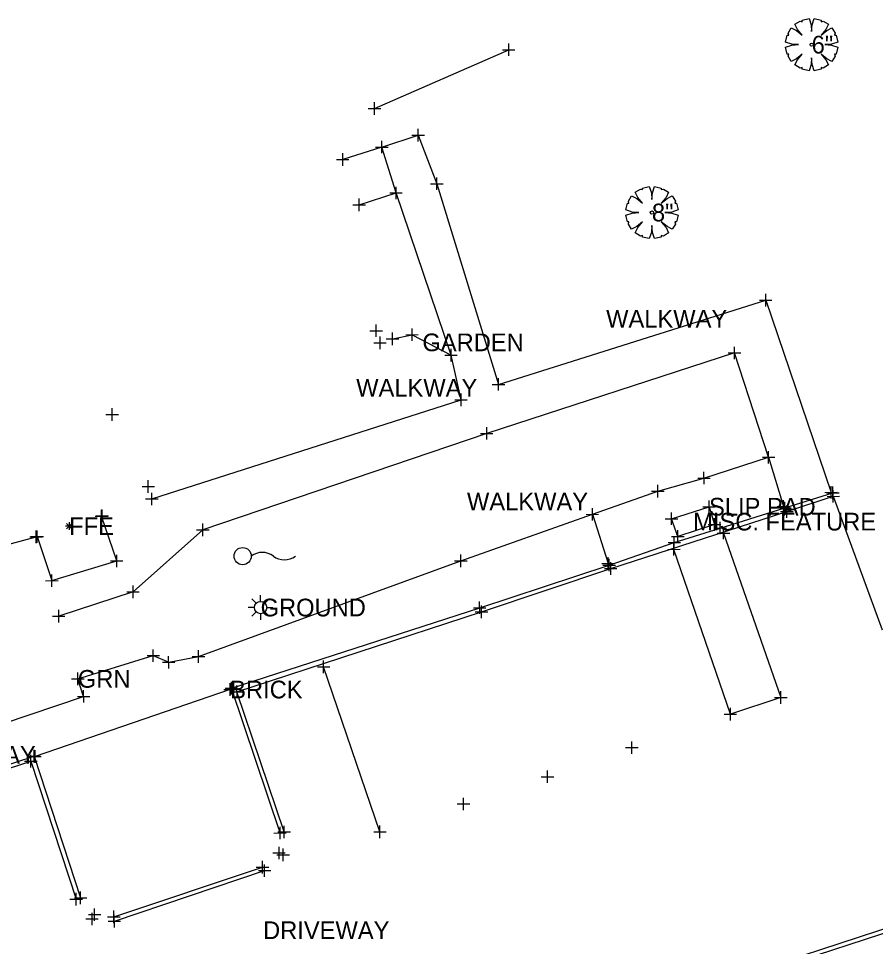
# Model space of a CAD drawing. Extents: x 1729655 to 1739338, y 463812 to 469501.
# Drawn here: x 1734985 to 1735072.1, y 466921 to 467015.3 of the extents above; entities that cross this region are included whole.
import ezdxf

# ---------------------------------------------------------------- set-up
doc = ezdxf.new("R2010")
doc.units = 0
for name, color, linetype in [('S_Bridge_Column_Round', 7, 'Continuous'), ('S_Bridge_Deck', 7, 'Continuous'), ('S_Buildings_Steps', 7, 'Continuous'), ('S_Curb_Type_2', 7, 'Continuous'), ('S_Curb_Type_5', 7, 'Continuous'), ('S_Drainage_Invert_Culvert', 7, 'Continuous'), ('S_Ground_SpotElevation', 7, 'Continuous'), ('S_Property_Garden', 7, 'Continuous'), ('S_Roadway_Drive_Gravel', 7, 'Continuous'), ('S_Roadway_Edge_TW', 7, 'Continuous'), ('S_Roadway_Sidewalks', 7, 'Continuous'), ('S_Terrain_High_Points', 7, 'Continuous'), ('S_Trees_Decid_NonPay', 7, 'Continuous'), ('S_Trees_TreeLine', 7, 'Continuous'), ('S_Utilities_UG_Sanitary_MH', 7, 'Continuous')]:
    doc.layers.add(name, color=color, linetype=linetype)

msp = doc.modelspace()

# ---------------------------------------------------------------- linework, layer by layer
at = {"layer": 'S_Bridge_Column_Round'}
for p, q in [((1735034.805, 467011.529), (1735034.803, 467012.801)), ((1735034.168, 467012.164), (1735035.44, 467012.166)), ((1735034.804, 467012.165), (1735034.804, 467012.165)), ((1735020.534, 467006.184), (1735021.806, 467006.186)), ((1735021.171, 467005.549), (1735021.169, 467006.821)), ((1735021.17, 467006.185), (1735021.17, 467006.185)), ((1735025.604, 467002.846), (1735025.602, 467004.118)), ((1735024.967, 467003.481), (1735026.239, 467003.483)), ((1735025.603, 467003.482), (1735025.603, 467003.482)), ((1735021.283, 467002.269), (1735022.555, 467002.271)), ((1735021.283, 467002.269), (1735022.555, 467002.271)), ((1735021.92, 467001.634), (1735021.918, 467002.906)), ((1735021.92, 467001.634), (1735021.918, 467002.906)), ((1735021.919, 467002.27), (1735021.919, 467002.27)), ((1735021.919, 467002.27), (1735021.919, 467002.27)), ((1735017.934, 467000.375), (1735017.932, 467001.647)), ((1735017.297, 467001.01), (1735018.569, 467001.012)), ((1735017.933, 467001.011), (1735017.933, 467001.011)), ((1735026.855, 466998.541), (1735028.127, 466998.543)), ((1735027.492, 466997.906), (1735027.49, 466999.178)), ((1735027.491, 466998.542), (1735027.491, 466998.542)), ((1735022.717, 466997.605), (1735023.989, 466997.607)), ((1735022.717, 466997.605), (1735023.989, 466997.607)), ((1735023.354, 466996.97), (1735023.352, 466998.242)), ((1735023.354, 466996.97), (1735023.352, 466998.242)), ((1735023.353, 466997.606), (1735023.353, 466997.606)), ((1735023.353, 466997.606), (1735023.353, 466997.606)), ((1735019.613, 466995.766), (1735019.611, 466997.038)), ((1735018.976, 466996.401), (1735020.248, 466996.403)), ((1735019.612, 466996.402), (1735019.612, 466996.402)), ((1735060.922, 466986.063), (1735060.92, 466987.335)), ((1735060.285, 466986.698), (1735061.557, 466986.7)), ((1735060.921, 466986.699), (1735060.921, 466986.699)), ((1735020.7, 466983.598), (1735021.972, 466983.6)), ((1735021.337, 466982.963), (1735021.335, 466984.235)), ((1735021.336, 466983.599), (1735021.336, 466983.599)), ((1735022.986, 466982.13), (1735022.984, 466983.402)), ((1735022.986, 466982.13), (1735022.984, 466983.402)), ((1735024.979, 466982.56), (1735024.977, 466983.832)), ((1735021.093, 466982.369), (1735022.365, 466982.371)), ((1735021.73, 466981.734), (1735021.728, 466983.006)), ((1735021.729, 466982.37), (1735021.729, 466982.37)), ((1735022.349, 466982.765), (1735023.621, 466982.767)), ((1735022.349, 466982.765), (1735023.621, 466982.767)), ((1735022.985, 466982.766), (1735022.985, 466982.766)), ((1735022.985, 466982.766), (1735022.985, 466982.766)), ((1735024.342, 466983.195), (1735025.614, 466983.197)), ((1735024.978, 466983.196), (1735024.978, 466983.196)), ((1735028.946, 466980.48), (1735028.944, 466981.752)), ((1735028.946, 466980.48), (1735028.944, 466981.752)), ((1735057.745, 466980.703), (1735057.743, 466981.975)), ((1735028.309, 466981.115), (1735029.581, 466981.117)), ((1735028.309, 466981.115), (1735029.581, 466981.117)), ((1735028.945, 466981.116), (1735028.945, 466981.116)), ((1735028.945, 466981.116), (1735028.945, 466981.116)), ((1735057.108, 466981.338), (1735058.38, 466981.34)), ((1735057.744, 466981.339), (1735057.744, 466981.339)), ((1735033.759, 466977.505), (1735033.757, 466978.777)), ((1735033.122, 466978.14), (1735034.394, 466978.142)), ((1735033.758, 466978.141), (1735033.758, 466978.141)), ((1735029.959, 466975.944), (1735029.957, 466977.216)), ((1735029.322, 466976.579), (1735030.594, 466976.581)), ((1735029.958, 466976.58), (1735029.958, 466976.58)), ((1734993.876, 466975.072), (1734995.148, 466975.074)), ((1734994.513, 466974.437), (1734994.511, 466975.709)), ((1734994.512, 466975.073), (1734994.512, 466975.073)), ((1735031.928, 466973.163), (1735033.2, 466973.165)), ((1735032.565, 466972.528), (1735032.563, 466973.8)), ((1735032.564, 466973.164), (1735032.564, 466973.164)), ((1735061.214, 466970.095), (1735061.212, 466971.367)), ((1735061.214, 466970.095), (1735061.212, 466971.367)), ((1735060.577, 466970.73), (1735061.849, 466970.732)), ((1735060.577, 466970.73), (1735061.849, 466970.732)), ((1735061.213, 466970.731), (1735061.213, 466970.731)), ((1735061.213, 466970.731), (1735061.213, 466970.731)), ((1735054.648, 466967.985), (1735054.646, 466969.257)), ((1734998.177, 466967.128), (1734998.175, 466968.4)), ((1735054.011, 466968.62), (1735055.283, 466968.622)), ((1735054.647, 466968.621), (1735054.647, 466968.621)), ((1734997.54, 466967.763), (1734998.812, 466967.765)), ((1734998.176, 466967.764), (1734998.176, 466967.764)), ((1735049.322, 466967.286), (1735050.594, 466967.288)), ((1735049.959, 466966.651), (1735049.957, 466967.923)), ((1735049.958, 466967.287), (1735049.958, 466967.287)), ((1735067.559, 466966.531), (1735067.557, 466967.803)), ((1735067.732, 466966.488), (1735067.73, 466967.76)), ((1735067.784, 466966.125), (1735067.782, 466967.397)), ((1734997.91, 466966.492), (1734999.182, 466966.494)), ((1734997.91, 466966.492), (1734999.182, 466966.494)), ((1734998.547, 466965.857), (1734998.545, 466967.129)), ((1734998.547, 466965.857), (1734998.545, 466967.129)), ((1734998.546, 466966.493), (1734998.546, 466966.493)), ((1734998.546, 466966.493), (1734998.546, 466966.493)), ((1735055.161, 466965.065), (1735055.159, 466966.337)), ((1735062.715, 466965.088), (1735062.713, 466966.36)), ((1735066.922, 466967.166), (1735068.194, 466967.168)), ((1735067.095, 466967.123), (1735068.367, 466967.125)), ((1735067.147, 466966.76), (1735068.419, 466966.762)), ((1735067.558, 466967.167), (1735067.558, 466967.167)), ((1735067.731, 466967.124), (1735067.731, 466967.124)), ((1735067.783, 466966.761), (1735067.783, 466966.761)), ((1734993.427, 466964.111), (1734993.425, 466965.383)), ((1734993.508, 466964.156), (1734993.506, 466965.428)), ((1735043.306, 466964.295), (1735043.304, 466965.567)), ((1735043.306, 466964.295), (1735043.304, 466965.567)), ((1735054.524, 466965.7), (1735055.796, 466965.702)), ((1735055.16, 466965.701), (1735055.16, 466965.701)), ((1735062.078, 466965.723), (1735063.35, 466965.725)), ((1735062.229, 466965.581), (1735063.501, 466965.583)), ((1735062.714, 466965.724), (1735062.714, 466965.724)), ((1735062.866, 466964.946), (1735062.864, 466966.218)), ((1735062.865, 466965.582), (1735062.865, 466965.582)), ((1735063.06, 466964.57), (1735063.058, 466965.842)), ((1734992.79, 466964.746), (1734994.062, 466964.748)), ((1734992.871, 466964.791), (1734994.143, 466964.793)), ((1734993.426, 466964.747), (1734993.426, 466964.747)), ((1734993.507, 466964.792), (1734993.507, 466964.792)), ((1735042.669, 466964.93), (1735043.941, 466964.932)), ((1735042.669, 466964.93), (1735043.941, 466964.932)), ((1735043.305, 466964.931), (1735043.305, 466964.931)), ((1735043.305, 466964.931), (1735043.305, 466964.931)), ((1735050.714, 466964.483), (1735051.986, 466964.485)), ((1735051.351, 466963.848), (1735051.349, 466965.12)), ((1735051.35, 466964.484), (1735051.35, 466964.484)), ((1735055.715, 466963.254), (1735055.713, 466964.526)), ((1735062.423, 466965.205), (1735063.695, 466965.207)), ((1735063.059, 466965.206), (1735063.059, 466965.206)), ((1735003.721, 466962.716), (1735003.719, 466963.988)), ((1735055.078, 466963.889), (1735056.35, 466963.891)), ((1735055.652, 466963.54), (1735056.924, 466963.542)), ((1735055.714, 466963.89), (1735055.714, 466963.89)), ((1735056.289, 466962.905), (1735056.287, 466964.177)), ((1735056.288, 466963.541), (1735056.288, 466963.541)), ((1735056.624, 466962.395), (1735056.622, 466963.667)), ((1734986.134, 466962.645), (1734987.406, 466962.647)), ((1734986.247, 466962.666), (1734987.519, 466962.668)), ((1734986.771, 466962.01), (1734986.769, 466963.282)), ((1734986.77, 466962.646), (1734986.77, 466962.646)), ((1734986.884, 466962.031), (1734986.882, 466963.303)), ((1734986.883, 466962.667), (1734986.883, 466962.667)), ((1735003.084, 466963.351), (1735004.356, 466963.353)), ((1735003.72, 466963.352), (1735003.72, 466963.352)), ((1735051.358, 466962.667), (1735052.63, 466962.669)), ((1735051.629, 466961.417), (1735051.627, 466962.689)), ((1735051.995, 466962.032), (1735051.993, 466963.304)), ((1735051.994, 466962.668), (1735051.994, 466962.668)), ((1735055.987, 466963.03), (1735057.259, 466963.032)), ((1735056.623, 466963.031), (1735056.623, 466963.031)), ((1735050.992, 466962.052), (1735052.264, 466962.054)), ((1735051.598, 466960.736), (1735051.596, 466962.008)), ((1735051.628, 466962.053), (1735051.628, 466962.053)), ((1734994.971, 466959.557), (1734994.969, 466960.829)), ((1735029.941, 466959.563), (1735029.939, 466960.835)), ((1735050.961, 466961.371), (1735052.233, 466961.373)), ((1735051.597, 466961.372), (1735051.597, 466961.372)), ((1734994.334, 466960.192), (1734995.606, 466960.194)), ((1734994.97, 466960.193), (1734994.97, 466960.193)), ((1735029.304, 466960.198), (1735030.576, 466960.2)), ((1735029.94, 466960.199), (1735029.94, 466960.199)), ((1735044.258, 466959.929), (1735045.53, 466959.931)), ((1735044.376, 466959.775), (1735045.648, 466959.777)), ((1735044.895, 466959.294), (1735044.893, 466960.566)), ((1735044.894, 466959.93), (1735044.894, 466959.93)), ((1735045.013, 466959.14), (1735045.011, 466960.412)), ((1735045.012, 466959.776), (1735045.012, 466959.776)), ((1735045.17, 466958.784), (1735045.168, 466960.056)), ((1734988.386, 466957.551), (1734988.384, 466958.823)), ((1735044.533, 466959.419), (1735045.805, 466959.421)), ((1735045.169, 466959.42), (1735045.169, 466959.42)), ((1734987.749, 466958.186), (1734989.021, 466958.188)), ((1734988.385, 466958.187), (1734988.385, 466958.187)), ((1734995.994, 466957.057), (1734997.266, 466957.059)), ((1734995.994, 466957.057), (1734997.266, 466957.059)), ((1734996.631, 466956.422), (1734996.629, 466957.694)), ((1734996.631, 466956.422), (1734996.629, 466957.694)), ((1734996.63, 466957.058), (1734996.63, 466957.058)), ((1734996.63, 466957.058), (1734996.63, 466957.058)), ((1735031.853, 466954.803), (1735031.851, 466956.075)), ((1734989.076, 466953.949), (1734989.074, 466955.221)), ((1734989.076, 466953.949), (1734989.074, 466955.221)), ((1734989.076, 466953.949), (1734989.074, 466955.221)), ((1735031.216, 466955.438), (1735032.488, 466955.44)), ((1735031.407, 466955.016), (1735032.679, 466955.018)), ((1735031.852, 466955.439), (1735031.852, 466955.439)), ((1735032.044, 466954.381), (1735032.042, 466955.653)), ((1735032.043, 466955.017), (1735032.043, 466955.017)), ((1734988.439, 466954.584), (1734989.711, 466954.586)), ((1734988.439, 466954.584), (1734989.711, 466954.586)), ((1734988.439, 466954.584), (1734989.711, 466954.586)), ((1734989.075, 466954.585), (1734989.075, 466954.585)), ((1734989.075, 466954.585), (1734989.075, 466954.585)), ((1734989.075, 466954.585), (1734989.075, 466954.585)), ((1734998.05, 466950.567), (1734999.322, 466950.569)), ((1734998.05, 466950.567), (1734999.322, 466950.569)), ((1734998.687, 466949.932), (1734998.685, 466951.204)), ((1734998.687, 466949.932), (1734998.685, 466951.204)), ((1734998.686, 466950.568), (1734998.686, 466950.568)), ((1734998.686, 466950.568), (1734998.686, 466950.568)), ((1735000.25, 466949.252), (1735000.248, 466950.524)), ((1735002.639, 466950.47), (1735003.911, 466950.472)), ((1735003.276, 466949.835), (1735003.274, 466951.107)), ((1735003.275, 466950.471), (1735003.275, 466950.471)), ((1734999.613, 466949.887), (1735000.885, 466949.889)), ((1735000.249, 466949.888), (1735000.249, 466949.888)), ((1735015.357, 466949.433), (1735016.629, 466949.435)), ((1735015.994, 466948.798), (1735015.992, 466950.07)), ((1735015.993, 466949.434), (1735015.993, 466949.434)), ((1734991.019, 466947.568), (1734991.017, 466948.84)), ((1734991.019, 466947.568), (1734991.017, 466948.84)), ((1734990.382, 466948.203), (1734991.654, 466948.205)), ((1734990.382, 466948.203), (1734991.654, 466948.205)), ((1734991.018, 466948.204), (1734991.018, 466948.204)), ((1734991.018, 466948.204), (1734991.018, 466948.204)), ((1735006.502, 466946.484), (1735006.5, 466947.756)), ((1735006.623, 466946.619), (1735006.621, 466947.891)), ((1735007.193, 466946.246), (1735007.191, 466947.518)), ((1734991.611, 466945.789), (1734991.609, 466947.061)), ((1735005.865, 466947.119), (1735007.137, 466947.121)), ((1735005.986, 466947.254), (1735007.258, 466947.256)), ((1735006.501, 466947.12), (1735006.501, 466947.12)), ((1735006.556, 466946.881), (1735007.828, 466946.883)), ((1735006.622, 466947.255), (1735006.622, 466947.255)), ((1735007.192, 466946.882), (1735007.192, 466946.882)), ((1735062.461, 466945.68), (1735062.459, 466946.952)), ((1734990.974, 466946.424), (1734992.246, 466946.426)), ((1734991.61, 466946.425), (1734991.61, 466946.425)), ((1735061.824, 466946.315), (1735063.096, 466946.317)), ((1735062.46, 466946.316), (1735062.46, 466946.316)), ((1735057.33, 466943.972), (1735057.328, 466945.244)), ((1735056.693, 466944.607), (1735057.965, 466944.609)), ((1735057.329, 466944.608), (1735057.329, 466944.608)), ((1735047.307, 466940.58), (1735047.305, 466941.852)), ((1734986.567, 466939.704), (1734986.565, 466940.976)), ((1734986.668, 466939.676), (1734986.666, 466940.948)), ((1735046.67, 466941.215), (1735047.942, 466941.217)), ((1735047.306, 466941.216), (1735047.306, 466941.216)), ((1734985.93, 466940.339), (1734987.202, 466940.341)), ((1734986.031, 466940.311), (1734987.303, 466940.313)), ((1734986.248, 466939.199), (1734986.246, 466940.471)), ((1734986.566, 466940.34), (1734986.566, 466940.34)), ((1734986.667, 466940.312), (1734986.667, 466940.312)), ((1734985.611, 466939.834), (1734986.883, 466939.836)), ((1734986.247, 466939.835), (1734986.247, 466939.835)), ((1735038.113, 466938.257), (1735039.385, 466938.259)), ((1735038.75, 466937.622), (1735038.748, 466938.894)), ((1735038.749, 466938.258), (1735038.749, 466938.258)), ((1735029.568, 466935.487), (1735030.84, 466935.489)), ((1735030.205, 466934.852), (1735030.203, 466936.124)), ((1735030.204, 466935.488), (1735030.204, 466935.488)), ((1735010.931, 466932.532), (1735012.203, 466932.534)), ((1735011.34, 466932.636), (1735012.612, 466932.638)), ((1735011.568, 466931.897), (1735011.566, 466933.169)), ((1735011.567, 466932.533), (1735011.567, 466932.533)), ((1735011.977, 466932.001), (1735011.975, 466933.273)), ((1735011.976, 466932.637), (1735011.976, 466932.637)), ((1735021.083, 466932.651), (1735022.355, 466932.653)), ((1735021.72, 466932.016), (1735021.718, 466933.288)), ((1735021.719, 466932.652), (1735021.719, 466932.652)), ((1735010.828, 466930.505), (1735012.1, 466930.507)), ((1735011.465, 466929.87), (1735011.463, 466931.142)), ((1735011.464, 466930.506), (1735011.464, 466930.506)), ((1735011.878, 466929.684), (1735011.876, 466930.956)), ((1735009.792, 466928.43), (1735009.79, 466929.702)), ((1735011.241, 466930.319), (1735012.513, 466930.321)), ((1735011.877, 466930.32), (1735011.877, 466930.32)), ((1735009.155, 466929.065), (1735010.427, 466929.067)), ((1735009.361, 466928.705), (1735010.633, 466928.707)), ((1735009.791, 466929.066), (1735009.791, 466929.066)), ((1735009.998, 466928.07), (1735009.996, 466929.342)), ((1735009.997, 466928.706), (1735009.997, 466928.706)), ((1734990.214, 466925.8), (1734991.486, 466925.802)), ((1734990.664, 466925.936), (1734991.936, 466925.938)), ((1734990.851, 466925.165), (1734990.849, 466926.437)), ((1734990.85, 466925.801), (1734990.85, 466925.801)), ((1734991.301, 466925.301), (1734991.299, 466926.573)), ((1734991.3, 466925.937), (1734991.3, 466925.937)), ((1734992.725, 466923.596), (1734992.723, 466924.868)), ((1734992.088, 466924.231), (1734993.36, 466924.233)), ((1734992.461, 466923.158), (1734992.459, 466924.43)), ((1734992.724, 466924.232), (1734992.724, 466924.232)), ((1734994.046, 466924.015), (1734995.318, 466924.017)), ((1734994.683, 466923.38), (1734994.681, 466924.652)), ((1734994.682, 466924.016), (1734994.682, 466924.016)), ((1734994.729, 466922.939), (1734994.727, 466924.211)), ((1734991.824, 466923.793), (1734993.096, 466923.795)), ((1734992.46, 466923.794), (1734992.46, 466923.794)), ((1734994.092, 466923.574), (1734995.364, 466923.576)), ((1734994.728, 466923.575), (1734994.728, 466923.575))]:
    msp.add_line(p, q, dxfattribs=at)
at = {"layer": 'S_Bridge_Deck'}
for p, q in [((1735009.149, 466955.896), (1735008.708, 466956.337)), ((1735009.59, 466956.079), (1735009.59, 466956.703)), ((1735010.031, 466955.896), (1735010.472, 466956.337)), ((1735008.966, 466955.455), (1735008.342, 466955.455)), ((1735009.149, 466955.014), (1735008.708, 466954.573)), ((1735010.031, 466955.014), (1735010.472, 466954.573)), ((1735010.214, 466955.455), (1735010.838, 466955.455)), ((1735009.59, 466954.831), (1735009.59, 466954.207))]:
    msp.add_line(p, q, dxfattribs=at)
msp.add_circle((1735009.59, 466955.455), 0.624, dxfattribs=at)
at = {"layer": 'S_Buildings_Steps'}
for p, q in [((1734990.534, 466963.731), (1734989.748, 466963.731)), ((1734990.403, 466963.469), (1734989.879, 466963.993)), ((1734990.403, 466963.993), (1734989.879, 466963.469)), ((1734990.141, 466964.124), (1734990.141, 466963.338))]:
    msp.add_line(p, q, dxfattribs=at)
at = {"layer": 'S_Curb_Type_2'}
msp.add_circle((1735007.767, 466960.685), 0.873, dxfattribs=at)
for centre, start, end in [((1735009.763, 466959.188), 53.1301, 126.8699), ((1735012.009, 466962.182), 233.1301, 306.8699)]:
    msp.add_arc(centre, 1.871, start, end, dxfattribs=at)
at = {"layer": 'S_Curb_Type_5'}
for points in [[(1735064.26, 467012.682), (1735063.571, 467012.735), (1735062.934, 467012.947), (1735063.093, 467013.637), (1735063.252, 467013.637), (1735063.199, 467013.849), (1735063.517, 467014.379), (1735064.047, 467014.114), (1735064.632, 467013.637), (1735064.154, 467014.22), (1735063.889, 467014.751), (1735064.419, 467015.069), (1735064.632, 467015.016), (1735064.632, 467015.175), (1735065.321, 467015.334), (1735065.533, 467014.698), (1735065.586, 467014.008), (1735065.639, 467014.698), (1735065.851, 467015.334), (1735066.541, 467015.175), (1735066.541, 467015.016), (1735066.753, 467015.069), (1735067.284, 467014.751), (1735067.018, 467014.22), (1735066.541, 467013.637), (1735067.124, 467014.114), (1735067.654, 467014.379), (1735067.973, 467013.849), (1735067.92, 467013.637), (1735068.079, 467013.637), (1735068.239, 467012.947), (1735067.602, 467012.735), (1735066.912, 467012.682), (1735067.602, 467012.629), (1735068.239, 467012.417), (1735068.079, 467011.727), (1735067.92, 467011.727), (1735067.973, 467011.515), (1735067.654, 467010.985), (1735067.124, 467011.25), (1735066.541, 467011.727), (1735067.018, 467011.144), (1735067.284, 467010.613), (1735066.753, 467010.295), (1735066.541, 467010.348), (1735066.541, 467010.189), (1735065.851, 467010.03), (1735065.639, 467010.666), (1735065.586, 467011.356), (1735065.533, 467010.666), (1735065.321, 467010.03), (1735064.632, 467010.189), (1735064.632, 467010.348), (1735064.419, 467010.295), (1735063.889, 467010.613), (1735064.154, 467011.144), (1735064.632, 467011.727), (1735064.047, 467011.25), (1735063.517, 467010.985), (1735063.199, 467011.515), (1735063.252, 467011.727), (1735063.093, 467011.727), (1735062.934, 467012.417), (1735063.571, 467012.629), (1735064.26, 467012.682)], [(1735048.031, 466995.614), (1735047.342, 466995.667), (1735046.705, 466995.879), (1735046.864, 466996.569), (1735047.023, 466996.569), (1735046.97, 466996.781), (1735047.288, 466997.311), (1735047.818, 466997.046), (1735048.403, 466996.569), (1735047.925, 466997.152), (1735047.66, 466997.683), (1735048.19, 466998.001), (1735048.403, 466997.948), (1735048.403, 466998.107), (1735049.092, 466998.266), (1735049.304, 466997.63), (1735049.357, 466996.94), (1735049.41, 466997.63), (1735049.622, 466998.266), (1735050.312, 466998.107), (1735050.312, 466997.948), (1735050.524, 466998.001), (1735051.055, 466997.683), (1735050.789, 466997.152), (1735050.312, 466996.569), (1735050.895, 466997.046), (1735051.425, 466997.311), (1735051.744, 466996.781), (1735051.691, 466996.569), (1735051.85, 466996.569), (1735052.01, 466995.879), (1735051.373, 466995.667), (1735050.683, 466995.614), (1735051.373, 466995.561), (1735052.01, 466995.349), (1735051.85, 466994.659), (1735051.691, 466994.659), (1735051.744, 466994.447), (1735051.425, 466993.917), (1735050.895, 466994.182), (1735050.312, 466994.659), (1735050.789, 466994.076), (1735051.055, 466993.545), (1735050.524, 466993.227), (1735050.312, 466993.28), (1735050.312, 466993.121), (1735049.622, 466992.962), (1735049.41, 466993.598), (1735049.357, 466994.288), (1735049.304, 466993.598), (1735049.092, 466992.962), (1735048.403, 466993.121), (1735048.403, 466993.28), (1735048.19, 466993.227), (1735047.66, 466993.545), (1735047.925, 466994.076), (1735048.403, 466994.659), (1735047.818, 466994.182), (1735047.288, 466993.917), (1735046.97, 466994.447), (1735047.023, 466994.659), (1735046.864, 466994.659), (1735046.705, 466995.349), (1735047.342, 466995.561), (1735048.031, 466995.614)]]:
    msp.add_lwpolyline(points, dxfattribs=at)
for centre in [(1735065.586, 467012.682), (1735049.357, 466995.614)]:
    msp.add_circle(centre, 0.166, dxfattribs=at)
at = {"layer": 'S_Drainage_Invert_Culvert'}
msp.add_lwpolyline([(1735022.985, 466982.766), (1735024.978, 466983.196), (1735028.945, 466981.116)], dxfattribs=at)
at = {"layer": 'S_Ground_SpotElevation'}
for p, q in [((1735063.059, 466965.206), (1735067.783, 466966.761)), ((1735067.783, 466966.761), (1735072.74, 466953.186)), ((1735045.169, 466959.42), (1735063.059, 466965.206)), ((1735032.043, 466955.017), (1735045.169, 466959.42)), ((1735007.192, 466946.882), (1735032.043, 466955.017)), ((1735011.976, 466932.637), (1735007.192, 466946.882)), ((1734959.798, 466931.066), (1734986.247, 466939.835)), ((1734986.247, 466939.835), (1734990.85, 466925.801)), ((1734994.728, 466923.575), (1735009.997, 466928.706)), ((1735092.82, 466929.33), (1735062.66, 466919.391))]:
    msp.add_line(p, q, dxfattribs=at)
at = {"layer": 'S_Property_Garden'}
for points in [[(1735021.919, 467002.27), (1735025.603, 467003.482), (1735027.491, 466998.542), (1735033.758, 466978.141), (1735060.921, 466986.699), (1735067.558, 466967.167)], [(1734998.546, 466966.493), (1735029.958, 466976.58), (1735028.945, 466981.116), (1735023.353, 466997.606)], [(1734998.686, 466950.568), (1735000.249, 466949.888), (1735003.275, 466950.471), (1735029.94, 466960.199), (1735043.305, 466964.931), (1735049.958, 466967.287), (1735054.647, 466968.621), (1735061.213, 466970.731), (1735057.744, 466981.339), (1735032.564, 466973.164), (1735003.72, 466963.352), (1734996.63, 466957.058)], [(1734950.694, 466952.682), (1734952.406, 466952.401), (1734980.826, 466960.286), (1734981.723, 466961.277), (1734986.77, 466962.646)], [(1734959.91, 466931.635), (1734958.83, 466935.374), (1734991.61, 466946.425), (1734991.018, 466948.204)]]:
    msp.add_lwpolyline(points, dxfattribs=at)
at = {"layer": 'S_Roadway_Drive_Gravel'}
for points in [[(1735056.623, 466963.031), (1735062.46, 466946.316), (1735057.329, 466944.608), (1735051.597, 466961.372)], [(1735021.719, 466932.652), (1735015.993, 466949.434)]]:
    msp.add_lwpolyline(points, dxfattribs=at)
at = {"layer": 'S_Roadway_Edge_TW'}
for points in [[(1734996.63, 466957.058), (1734989.075, 466954.585)], [(1734991.018, 466948.204), (1734998.686, 466950.568)]]:
    msp.add_lwpolyline(points, dxfattribs=at)
at = {"layer": 'S_Roadway_Sidewalks'}
for points in [[(1735019.612, 466996.402), (1735023.353, 466997.606), (1735021.919, 467002.27), (1735017.933, 467001.011)], [(1735061.213, 466970.731), (1735062.714, 466965.724)], [(1734986.883, 466962.667), (1734988.385, 466958.187), (1734994.97, 466960.193), (1734993.426, 466964.747)], [(1735043.305, 466964.931), (1735044.894, 466959.93)], [(1735006.501, 466947.12), (1734986.667, 466940.312)]]:
    msp.add_lwpolyline(points, dxfattribs=at)
at = {"layer": 'S_Trees_Decid_NonPay'}
msp.add_lwpolyline([(1735055.16, 466965.701), (1735055.714, 466963.89), (1735051.994, 466962.668), (1735051.35, 466964.484)], close=True, dxfattribs=at)
at = {"layer": 'S_Trees_TreeLine'}
msp.add_lwpolyline([(1735021.17, 467006.185), (1735034.804, 467012.165)], dxfattribs=at)
at = {"layer": 'S_Utilities_UG_Sanitary_MH'}
for p, q in [((1735062.865, 466965.582), (1735067.731, 466967.124)), ((1735056.288, 466963.541), (1735062.865, 466965.582)), ((1735051.628, 466962.053), (1735056.288, 466963.541)), ((1735045.012, 466959.776), (1735051.628, 466962.053)), ((1735031.852, 466955.439), (1735045.012, 466959.776)), ((1735006.622, 466947.255), (1735031.852, 466955.439)), ((1735011.567, 466932.533), (1735006.622, 466947.255)), ((1734959.643, 466931.458), (1734986.566, 466940.34)), ((1734986.566, 466940.34), (1734991.3, 466925.937)), ((1734994.682, 466924.016), (1735009.791, 466929.066)), ((1735089.353, 466927.72), (1735062.829, 466919.041))]:
    msp.add_line(p, q, dxfattribs=at)

# ---------------------------------------------------------------- texts
at = {"layer": 'S_Terrain_High_Points'}
for s, p in [('6"', (1735065.586, 467011.782)), ('8"', (1735049.357, 466994.714)), ('WALKWAY', (1735044.702, 466983.918)), ('GARDEN', (1735026.032, 466981.513)), ('WALKWAY', (1735019.305, 466976.902)), ('WALKWAY', (1735030.562, 466965.329)), ('SLIP PAD', (1735055.16, 466964.801)), ('FFE', (1734990.141, 466962.831)), ('MISC. FEATURE', (1735053.548, 466963.287)), ('GROUND', (1735009.59, 466954.555)), ('GRN', (1734991.018, 466947.304)), ('GRN', (1734991.018, 466947.304)), ('BRICK', (1735006.501, 466946.22)), ('WALKWAY', (1734974.438, 466939.584)), ('DRIVEWAY', (1735009.843, 466921.748))]:
    msp.add_text(s, height=1.8, dxfattribs=at).set_placement(p)

doc.saveas('drawing.dxf')
